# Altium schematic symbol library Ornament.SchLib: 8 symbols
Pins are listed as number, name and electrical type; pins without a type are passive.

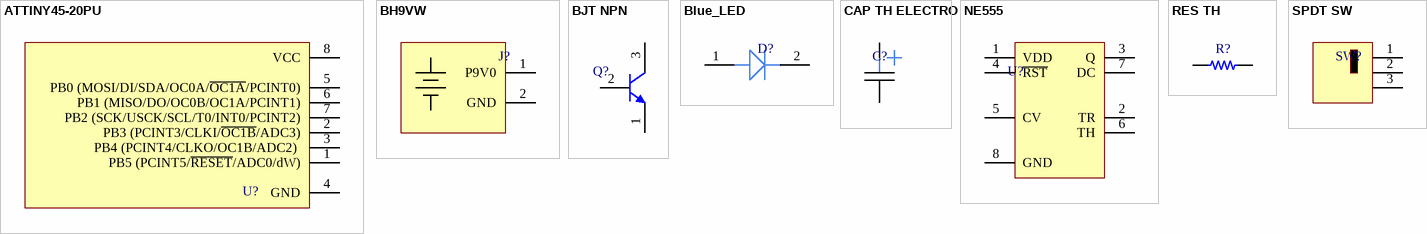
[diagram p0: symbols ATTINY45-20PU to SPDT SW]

## ATTINY45-20PU
designator U?  (value not drawn)
pins: 1 PB5 (PCINT5/~{RESET}/ADC0/dW), 2 PB3 (PCINT3/CLKI/~{OC1B}/ADC3), 3 PB4 (PCINT4/CLKO/OC1B/ADC2) , 4 GND, 5 PB0 (MOSI/DI/SDA/OC0A/~{OC1A}/PCINT0), 6 PB1 (MISO/DO/OC0B/OC1A/PCINT1), 7 PB2 (SCK/USCK/SCL/T0/INT0/PCINT2), 8 VCC

## BH9VW
designator J?, comment BATT HOLDER 9V  (value not drawn)
BATTERY HOLDER 9V 6" LEADS; ManufacturerPartNumber: BH9VW
footprint BH9VW (BH9VPC 9V Battery Holder Leaded)
pins: 1 P9V0, 2 GND

## BJT NPN
designator Q?, comment PN2222TA  (value not drawn)
footprint BJT NPN
pins: 1 E, 2 B, 3 C

## Blue_LED
designator D?, comment Blue LED  (value not drawn)
MPN: 3474AN-BADB-AGJA-PR-MS; Vfwd: 3.2
footprint BLUE_LED
pins: 1, 2

## CAP TH ELECTRO
designator C?  (value not drawn)
footprint CAP ELELCTROLYTIC TH
pins: 1, 2

## NE555
designator U?  (value not drawn)
MPN: NE555P
footprint 555 SOCKET (1-2199298-2)
pins: 1 VDD, 2 TR, 3 Q, 4 ~{RST}, 5 CV, 6 TH, 7 DC, 8 GND

## RES TH
designator R?  (value not drawn)
footprint RES TH (RES TH 400MIL)
pins: 1, 2

## SPDT SW
designator SW?, comment OS102011MS2QS1  (value not drawn)
footprint SPDT SW
pins: 1, 2, 3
